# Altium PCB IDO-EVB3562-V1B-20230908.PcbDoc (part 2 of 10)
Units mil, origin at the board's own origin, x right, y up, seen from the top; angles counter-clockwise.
Board outline 5314.96 x 3543.31 mil, 4 copper layers (TOP, L2-VCC, L3-GND, BOTTOM), stack 28.8 mil thick; 747 components, 560 nets, 2514 pads, 1964 vias.
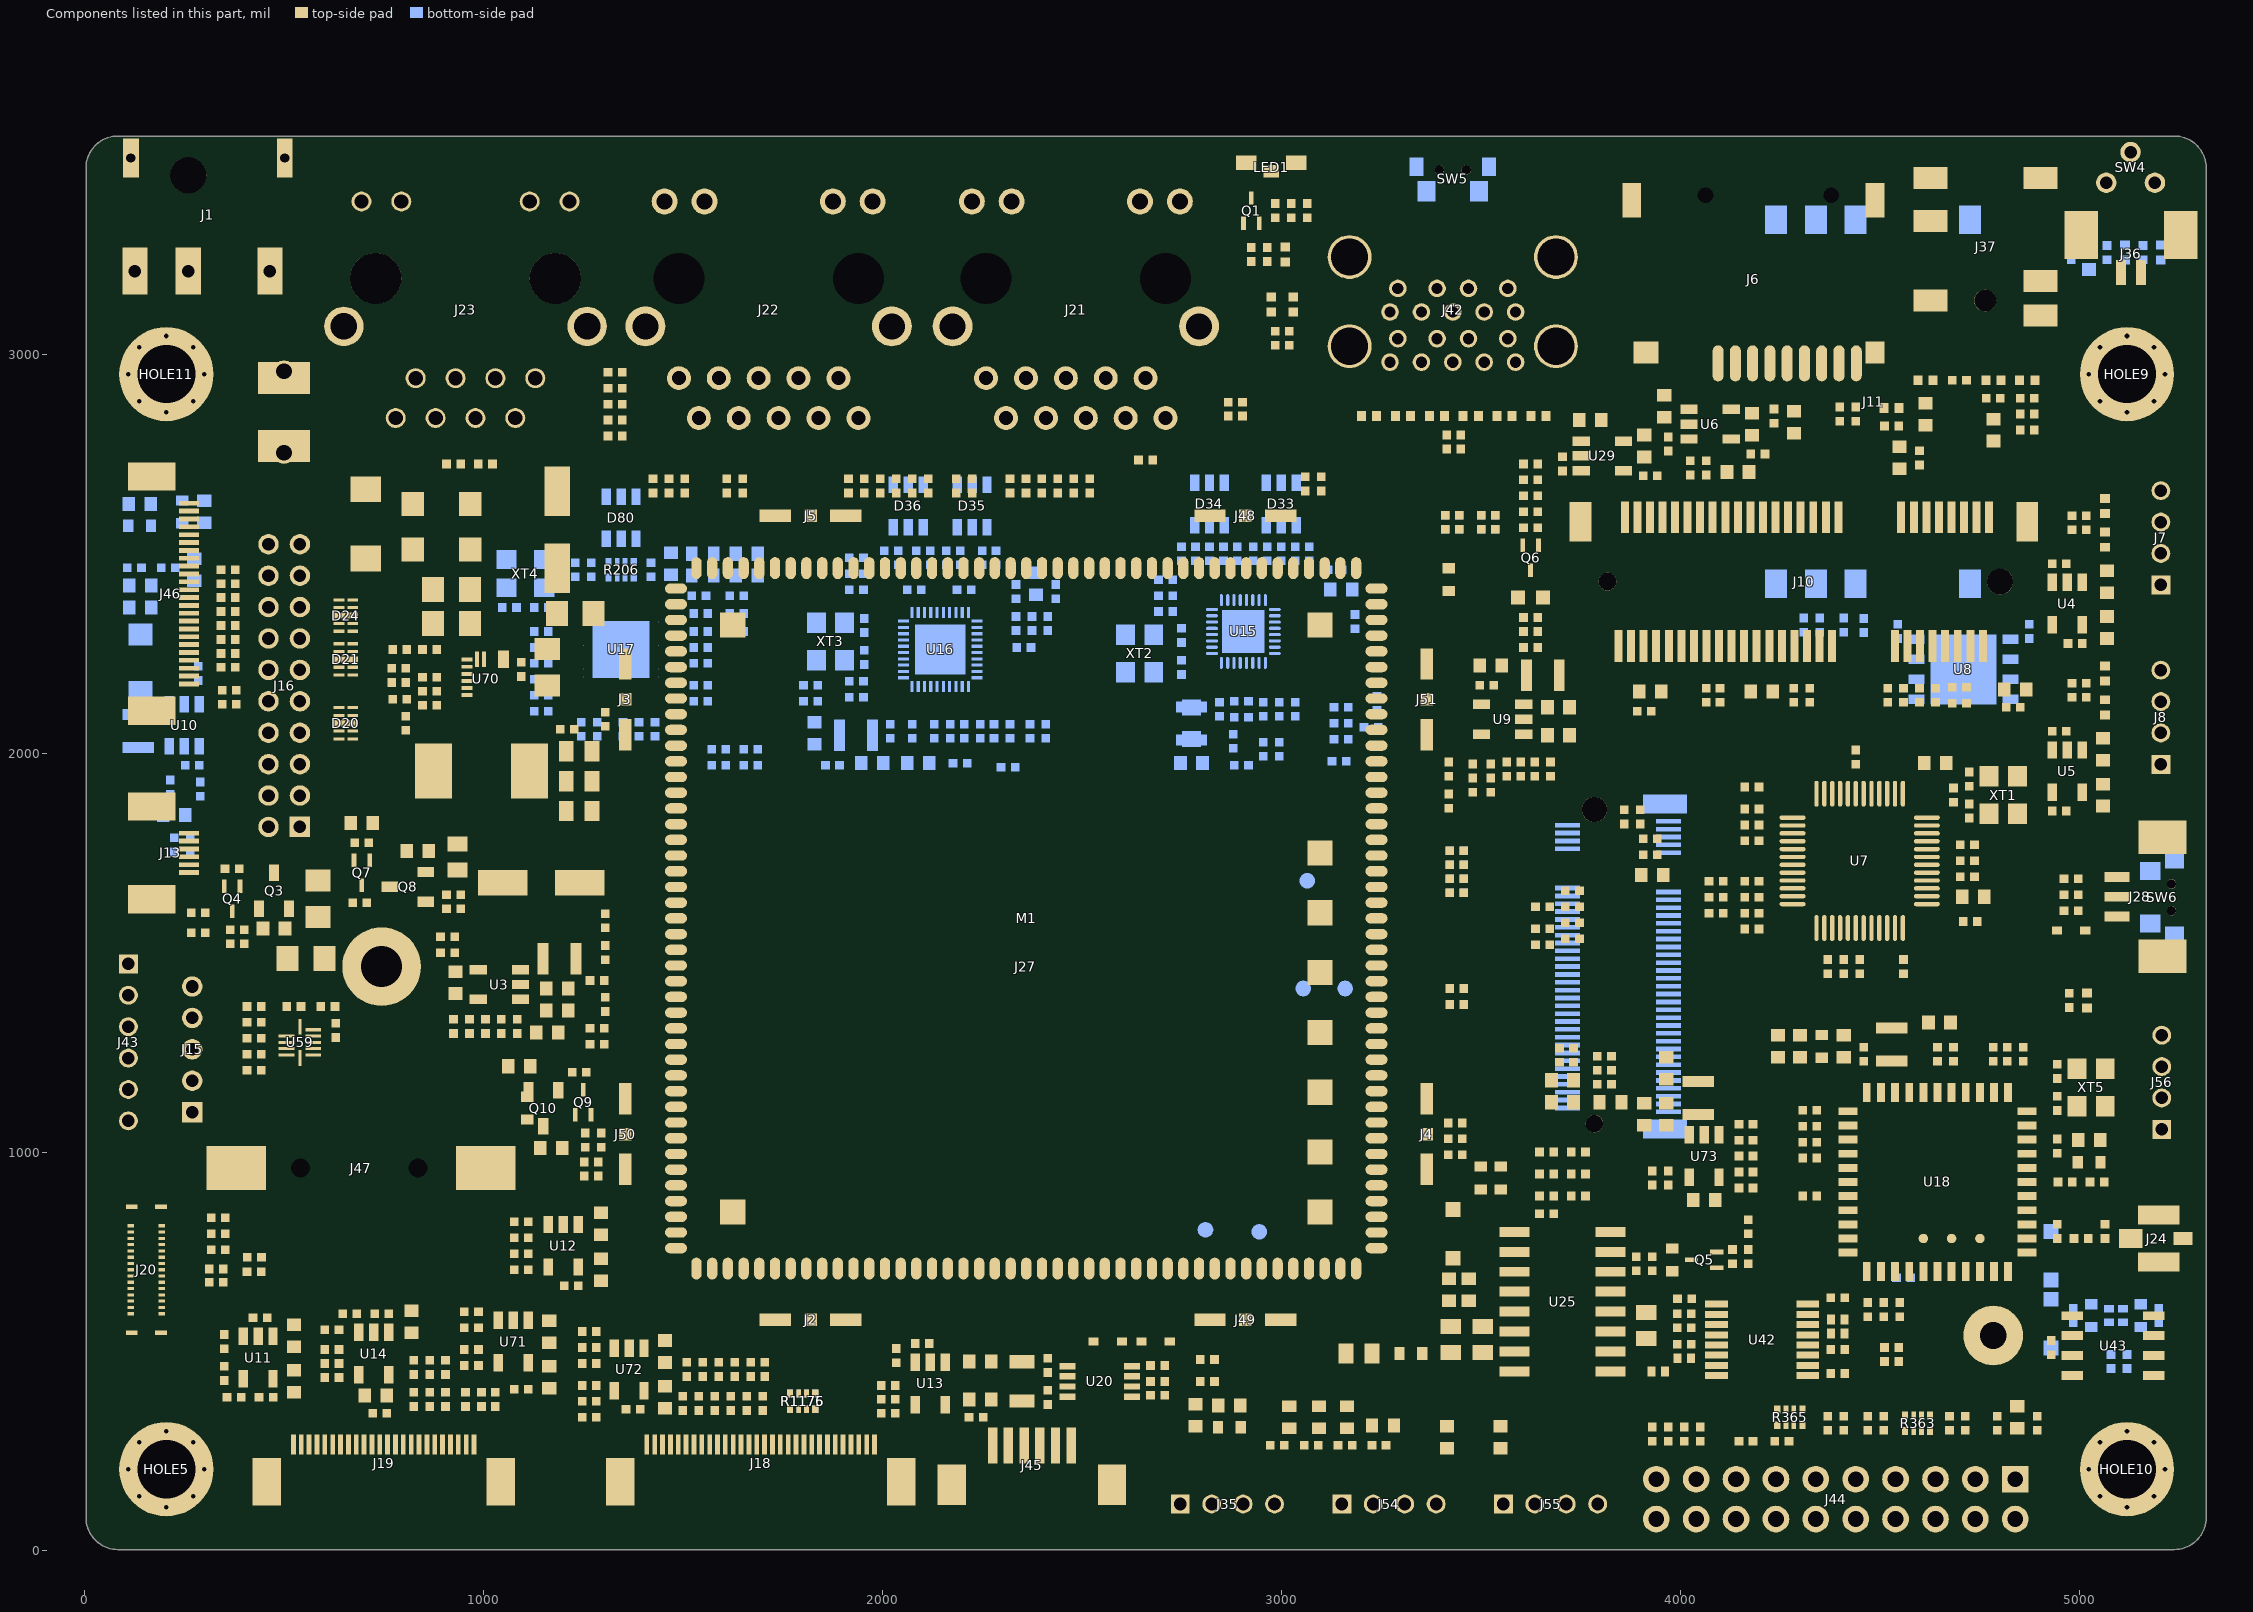
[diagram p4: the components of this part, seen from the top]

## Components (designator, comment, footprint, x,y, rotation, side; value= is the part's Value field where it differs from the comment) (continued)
SW4 "SW-3P_PB-SIDE-P-4_5X4_5_T-SWITC" ASSEMBLY_TOP#26 5128.98,3469.37 r270 top
SW5 "SW-TS24CA_PB-SIDE-S-3_5X4_5_T-S" SILKSCREEN_BOTTOM#6 3428.5,3440.5 r0 bottom
SW6 "SW-TS24CA_PB-SIDE-S-3_5X4_5_T-S" SILKSCREEN_BOTTOM#6 5210,1640 r270 bottom
TP1 "TP-TEST_TP100_TP100" ASSEMBLY_BOTTOM#7 3065,1680 r0 bottom
TP2 "TP-TEST_TP100_TP100" ASSEMBLY_BOTTOM#7 3055,1410 r0 bottom
TP3 "TP-TEST_TP100_TP100" ASSEMBLY_BOTTOM#7 3160,1410 r0 bottom
TP4 "TP-TEST_TP100_TP100" ASSEMBLY_BOTTOM#7 2945,800 r0 bottom
TP5 "TP-TEST_TP100_TP100" ASSEMBLY_BOTTOM#7 2810,805 r0 bottom
U3 "U-ETA3417S2F_SOT23-5_ETA3417S2F" SILKSCREEN_TOP#14 1040,1420 r180 top
U4 "U-SY6280AAC_SOT23-5_ETA6280S2F" SILKSCREEN_TOP#14 4970,2375 r270 top
U5 "U-SY6280AAC_SOT23-5_ETA6280S2F" SILKSCREEN_TOP#14 4970,1955 r270 top
U6 "U-SY6280AAC_SOT23-5_ETA6280S2F" ASSEMBLY_TOP#27 4075,2825 r0 top
U7 "U-FE1_1_LQFP-48_7X7X05P_FE1.1" ASSEMBLY_TOP#28 4450,1730 r180 top
U8 "ESIM_ESIM_NC/ESIM" ASSEMBLY_BOTTOM#8 4710,2210 r0 bottom
U9 "U-ETA3417S2F_SOT23-5_ETA3417S2F" SILKSCREEN_TOP#14 3555,2085 r180 top
U10 "U-SY7201ABC_SOT23-6_SY7201ABC" SILKSCREEN_BOTTOM#2 250,2070 r270 bottom
U11 "U-ETA5050_SOT23-5_ETA5050V0S2F" SILKSCREEN_TOP#14 435,485 r270 top
U12 "U-ETA5050_SOT23-5_ETA5050V0S2F" SILKSCREEN_TOP#14 1200,765 r270 top
U13 "U-ETA5050_SOT23-5_ETA5050V0S2F" SILKSCREEN_TOP#14 2120,420 r270 top
U14 "U-ETA5050_SOT23-5_ETA5050V0S2F" SILKSCREEN_TOP#14 725,495 r270 top
U15 "RL5877_0_QFN-32_4X4X04P_RTL8111" SILKSCREEN_BOTTOM#7 2905,2305 r270 bottom
U16 "U-RTL8211F-CG_QFN-40_5X5X04P_RT" SILKSCREEN_BOTTOM#8 2145,2260 r270 bottom
U17 "U-RTL8201F-VB-CG_QFN-32_5X5X05P" SILKSCREEN_BOTTOM#9 1345,2260 r270 bottom
U18 "MODULE_AP6XXX_MD44_AP6XXX_AP625" ASSEMBLY_TOP#29 4645,925 r180 top
U20 "U-HYM8563S_MSOP-8_HYM8563S" DISPLAY_TOP#17 2544.42,426.25 r0 top
U25 "U-NS4205_SOP16-P127-390X990_NS4" DISPLAY_TOP#18 3705,625 r180 top
U29 "U-SY6280AAC_SOT23-5_ETA6280S2F" SILKSCREEN_TOP#14 3805,2745 r0 top
U42 "U-SP3232EEN_TSSOP-16_HD3232ECY" ASSEMBLY_TOP#30 4205.5,529.14 r0 top
U43 "U-TJA1057GT-3J_SOP8-P127-390X49" ASSEMBLY_TOP#31 5085,515 r0 top
U59 "U-ETA4554QHM_ETA4554-QFN12_ETA4" ASSEMBLY_TOP#32 540,1275 r0 top
U70 "U-SY8368AQQC_6_QFN3X3-12-SY8368" SILKSCREEN_TOP#15 1010,2190 r90 top
U71 "U-ETA5050_SOT23-5_ETA5050V0S2F" SILKSCREEN_TOP#14 1075,525 r270 top
U72 "U-ETA5050_SOT23-5_ETA5050V0S2F" SILKSCREEN_TOP#14 1365,455 r270 top
U73 "U-ETA3417S2F_SOT23-5_ETA3417S2F" ASSEMBLY_TOP#27 4060,990 r270 top
XT1 "XTAL-4P_1_XTAL_32X25_4P_IC_12MH" SILKSCREEN_TOP#16 4810,1895 r180 top
XT2 "XTAL-4P_XTAL_32X25_4P_IC_25MHZ" ASSEMBLY_BOTTOM#9 2645,2250 r0 bottom
XT3 "XTAL-4P_XTAL_32X25_4P_IC_25MHZ" ASSEMBLY_BOTTOM#9 1870,2280 r0 bottom
XT4 "XTAL-4P_XTAL_32X25_4P_IC_25MHZ" ASSEMBLY_BOTTOM#10 1105,2450 r270 bottom
XT5 "XTAL-4P_XTAL_32X25_4P_IC_37.4MH" ASSEMBLY_TOP#33 5030,1162 r0 top
XT6 "XTAL-2P_XTAL_32X15_2P_IC_32.768" ASSEMBLY_TOP#34 2350,425 r270 top

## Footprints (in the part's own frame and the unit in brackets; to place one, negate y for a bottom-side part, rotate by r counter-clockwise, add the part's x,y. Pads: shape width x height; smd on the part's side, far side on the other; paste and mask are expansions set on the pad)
ASSEMBLY_BOTTOM#1 [mil] "ASSEMBLY_BOTTOM"
  rect 21.7x21.7 smd: 1(-17.72,0.01) 2(17.72,0.01)
  TOP keep-out region: -5,-14.99 -5,15.01 5,15.01 5,-14.99
  silkscreen extent -35,-16 35,16, body extent -35,-16 35,16, height 150
ASSEMBLY_BOTTOM#2 [mil] "ASSEMBLY_BOTTOM"
  rect 27.56x78.74 smd: 1(-40.84,0) 2(41.84,0)
  TOP keep-out region: -23.5,-40 -23.5,40 24.5,40 24.5,-40
  silkscreen extent -60,-45 60,45, body extent -58,-41 58,41, height 150
ASSEMBLY_BOTTOM#3 [mil] "ASSEMBLY_BOTTOM"
  rect 27.56x78.74 smd: 1(40.84,0) 2(-41.84,0)
  TOP keep-out region: 23.5,40 23.5,-40 -24.5,-40 -24.5,40 23.5,40
  silkscreen extent -60,-45 60,45, body extent -58,-41 58,41, height 150
ASSEMBLY_BOTTOM#4 [mil] "ASSEMBLY_BOTTOM"
  rect 27.56x78.74 smd: 1(-41.34,0) 2(41.34,0)
  TOP keep-out region: -24,-40 -24,40 24,40 24,-40 -24,-40
  silkscreen extent -60,-45 60,45
ASSEMBLY_BOTTOM#5 [mil] "ASSEMBLY_BOTTOM"
  rect 19.29x24.41 smd: 1(-16.93,0) 2(16.93,0)
  silkscreen extent -31,-16 31,16, body extent -31,-18 31,18, height 150
ASSEMBLY_BOTTOM#6 [mil] "ASSEMBLY_BOTTOM"
  rect 25.59x31.5 smd: 1(-28.54,0) 2(28.54,0)
  TOP keep-out region: -10,15 -10,-15 10,-15 10,15 -10,15
  silkscreen extent -53,-24 53,24, body extent -55,-25 55,25, height 150
ASSEMBLY_BOTTOM#7 [mil] "ASSEMBLY_BOTTOM"
  round 39.37 smd: 1(0,0)
  silkscreen extent -35,-35 35,35
ASSEMBLY_BOTTOM#8 [mil] "ASSEMBLY_BOTTOM"
  rect 40x24 smd: 1(118.11,-75) 2(118.11,-25) 3(118.11,25) 4(118.11,75) 5(-118.11,75) 6(-118.11,25) 7(-118.11,-25) 8(-118.11,-75)
  rect 166x176 smd: 9(0,0)
  silkscreen extent -118,-113 138,98, body extent -141,-101 141,101, height 150
ASSEMBLY_BOTTOM#9 [mil] "ASSEMBLY_BOTTOM"
  rect 47.24x51.18 smd: 1(35.43,-47.24) 2(35.43,47.24) 3(-35.43,47.24) 4(-35.43,-47.24)
  silkscreen extent -49,-63 76,63, body extent -59,-73 59,73, height 150
ASSEMBLY_BOTTOM#10 [mil] "ASSEMBLY_BOTTOM"
  rect 47.24x51.18 smd: 1(-35.43,47.24) 2(-35.43,-47.24) 3(35.43,-47.24) 4(35.43,47.24)
  silkscreen extent -76,-63 49,63, body extent -59,-73 59,73, height 150
ASSEMBLY_TOP#1 [mm] "ASSEMBLY_TOP"
  rect 3.15x1.6 smd: 1(-2.45,0) 2(2.45,0)
  silkscreen extent -3.92,-3.3 3.3,3.3, body extent -4.06,-3.9 4.55,3.43, height 3.81
ASSEMBLY_TOP#2 [mm] "ASSEMBLY_TOP"
  rect 0.8x0.899 smd: 1(-0.7,0) 2(0.7,0)
  silkscreen extent -1.35,-0.6 1.35,0.6, body extent -1.35,-0.6 1.35,0.6, height 3.81
ASSEMBLY_TOP#3 [mm] "ASSEMBLY_TOP"
  rect 0.551x0.551 smd: 1(-0.45,0) 2(0.45,0)
  TOP keep-out region: -0.127,-0.381 0.127,-0.381 0.127,0.381 -0.127,0.381 -0.127,-0.381
  silkscreen extent -0.9,-0.4 0.9,0.4, body extent -0.9,-0.4 0.9,0.4, height 3.81
ASSEMBLY_TOP#4 [mm] "ASSEMBLY_TOP"
  rect 0.95x1.3 smd: 1(-0.825,0) 2(0.825,0)
  silkscreen extent -1.7,-0.95 1.7,0.95, body extent -1.7,-0.95 1.7,0.95, height 3.81
ASSEMBLY_TOP#5 [mm] "ASSEMBLY_TOP"
  round 1.4 hole 0.991: 1(-2.591,0)
  round 1.4 / inner round 1.524 / far side round 1.4 hole 0.991: 2(2.591,0)
  silkscreen extent -6.86,-1.52 6.86,1.52, body extent -6.86,-1.52 6.86,1.52, height 3.81
ASSEMBLY_TOP#6 [mm] "ASSEMBLY_TOP"
  rect 2.032x3.302 smd: 1(-2.159,0) 2(2.159,0)
  TOP keep-out region: -1.6,1.699 -1.6,-1.699 1.6,-1.699 1.6,1.699 -1.6,1.699
  silkscreen extent -3.5,-1.9 3.5,1.9
ASSEMBLY_TOP#7 [mm] "ASSEMBLY_TOP"
  round 6 / inner round 1.524 / far side round 6 hole 3.7: 1(0,0)
  round 0.95 hole 0.3: ""(-2.425,0) ""(-1.715,-1.715) ""(-1.715,1.715) ""(0,-2.425) ""(0,2.425) ""(1.715,-1.715) ""(1.715,1.715)
  round 0 hole 0.3: ""(2.425,0)
  silkscreen extent -5.08,-5.08 5.08,5.08, body extent -3.01,-3.01 3.01,3.01, height 3.81
ASSEMBLY_TOP#8 [mm] "ASSEMBLY_TOP"
  rect 1.2x1.2 / inner round 1.524 / far side rect 1.2x1.2 hole 0.8: 1(3,-0.45)
  round 1.2 / inner round 1.524 / far side round 1.2 hole 0.8: 2(1,-0.45) 3(-1,-0.45)
  round 1.2 hole 0.8: 4(-3,-0.45)
  silkscreen extent -5,-2.25 5,2.25, body extent -5,-2.25 5,2.25, height 3.81
ASSEMBLY_TOP#9 [mm] "ASSEMBLY_TOP"
  rect 0.305x1.27 smd: 1(1.25,2.925) 2(0.75,2.925) 3(0.25,2.925) 4(-0.25,2.925) 5(-0.75,2.925) 6(-1.25,2.925)
  rect 1.803x3.048 smd: 7(2.95,0.55) 8(-2.95,0.55)
  silkscreen extent -4,-3.65 4,4.35, body extent -4,-3.65 4,3.65, height 3.81
ASSEMBLY_TOP#10 [mm] "ASSEMBLY_TOP"
  rect 1.3x1.3 / inner round 1 / far side rect 1.3x1.3 hole 0.8: 1(-4,0)
  round 1.3 / inner round 1.524 / far side round 1.3 hole 0.8: 2(-2,0) 3(0,0) 4(2,0)
  round 1.3 / inner round 1 / far side round 1.3 hole 0.8: 5(4,0)
  silkscreen extent -5,-2.15 5,1, body extent -5,-1 5,1, height 3.81
ASSEMBLY_TOP#11 [mm] "ASSEMBLY_TOP"
  rect 1.3x1.3 / inner round 1.524 / far side rect 1.3x1.3 hole 0.8: 1(-9,-1)
  round 1.3 / inner round 1.524 / far side round 1.3 hole 0.8: 2(-9,1) 3(-7,-1) 4(-7,1) 7(-3,-1) 8(-3,1) 9(-1,-1) 10(-1,1) 11(1,-1) 12(1,1) 15(5,-1) 16(5,1) 17(7,-1) 18(7,1) 19(9,-1) 20(9,1)
  round 1.3 / inner round 1 / far side round 1.3 hole 0.8: 5(-5,-1) 6(-5,1) 13(3,-1) 14(3,1)
  silkscreen extent -10,-3.1 10,2, body extent -10,-2 10,2, height 3.81
ASSEMBLY_TOP#12 [mm] "ASSEMBLY_TOP"
  rect 0.305x1.27 smd: 1(7.25,2.925) 2(6.75,2.925) 3(6.25,2.925) 4(5.75,2.925) 5(5.25,2.925) 6(4.75,2.925) 7(4.25,2.925) 8(3.75,2.925) 9(3.25,2.925) 10(2.75,2.925) 11(2.25,2.925) 12(1.75,2.925) 13(1.25,2.925) 14(0.75,2.925) 15(0.25,2.925) 16(-0.25,2.925) 17(-0.75,2.925) 18(-1.25,2.925) 19(-1.75,2.925) 20(-2.25,2.925) 21(-2.75,2.925) 22(-3.25,2.925) 23(-3.75,2.925) 24(-4.25,2.925) 25(-4.75,2.925) 26(-5.25,2.925) 27(-5.75,2.925) 28(-6.25,2.925) 29(-6.75,2.925) 30(-7.25,2.925)
  rect 1.803x3.048 smd: 31(8.95,0.55) 32(-8.95,0.55)
  silkscreen extent -10,-3.65 10.1,4.35, body extent -10,-3.65 10,3.65, height 3.81
ASSEMBLY_TOP#13 [mm] "ASSEMBLY_TOP"
  rect 0.305x1.27 smd: 1(5.75,2.925) 2(5.25,2.925) 3(4.75,2.925) 4(4.25,2.925) 5(3.75,2.925) 6(3.25,2.925) 7(2.75,2.925) 8(2.25,2.925) 9(1.75,2.925) 10(1.25,2.925) 11(0.75,2.925) 12(0.25,2.925) 13(-0.25,2.925) 14(-0.75,2.925) 15(-1.25,2.925) 16(-1.75,2.925) 17(-2.25,2.925) 18(-2.75,2.925) 19(-3.25,2.925) 20(-3.75,2.925) 21(-4.25,2.925) 22(-4.75,2.925) 23(-5.25,2.925) 24(-5.75,2.925)
  rect 1.803x3.048 smd: 25(7.45,0.55) 26(-7.45,0.55)
  silkscreen extent -8.5,-3.65 8.5,4.35, body extent -8.5,-3.65 8.5,3.65, height 3.81
ASSEMBLY_TOP#14 [mm] "ASSEMBLY_TOP"
  round 1.524 hole 0.889: 1(5.715,-9.14) 2(4.445,-6.6) 3(3.175,-9.14) 4(1.905,-6.6) 5(0.635,-9.14) 6(-0.635,-6.6) 7(-1.905,-9.14) 8(-3.175,-6.6) 9(-4.445,-9.14) 10(-5.715,-6.6)
  round 1.651 / inner round 1.524 / far side round 1.651 hole 1.016: 11(6.624,4.65) 12(4.084,4.65) 13(-4.084,4.65) 14(-6.624,4.65)
  round 2.54 hole 1.651: SH1(-7.846,-3.301) SH2(7.846,-3.301)
  round 2.997 hole 3.251 unplated: ""(-5.715,-0.25) ""(5.715,-0.25)
  Multi-Layer keep-out region: -3.495,-0.249 -3.537,0.184 -3.664,0.6 -3.869,0.984 -4.145,1.321 -4.481,1.597 -4.865,1.802 -5.282,1.928 -5.715,1.971 -6.148,1.928 -6.565,1.802 -6.82,1.665 -6.82,1.665 -6.949,1.597 -7.285,1.321 -7.561,0.984 -7.766,0.6 -7.893,0.184 -7.935,-0.249 -7.893,-0.683 -7.766,-1.099 -7.561,-1.483 -7.285,-1.82 -6.949,-2.096 -6.82,-2.164 -6.82,-2.164 -6.565,-2.301 -6.148,-2.427 -5.715,-2.47 -5.282,-2.427 -4.865,-2.301 -4.481,-2.096 -4.145,-1.82 -3.869,-1.483 -3.664,-1.099 -3.537,-0.683 -3.495,-0.249
  Multi-Layer keep-out region: 7.935,-0.249 7.893,0.184 7.766,0.6 7.561,0.984 7.285,1.321 6.949,1.597 6.565,1.802 6.148,1.928 5.715,1.971 5.282,1.928 4.865,1.802 4.61,1.665 4.61,1.665 4.481,1.597 4.145,1.321 3.869,0.984 3.664,0.6 3.537,0.184 3.495,-0.249 3.537,-0.683 3.664,-1.099 3.869,-1.483 4.145,-1.82 4.481,-2.096 4.61,-2.164 4.61,-2.164 4.865,-2.301 5.282,-2.427 5.715,-2.47 6.148,-2.427 6.565,-2.301 6.949,-2.096 7.285,-1.82 7.561,-1.483 7.766,-1.099 7.893,-0.683 7.935,-0.249
  silkscreen extent -8.1,-10.65 8.1,10.65, body extent -8.1,-10.65 8.1,10.65, height 3.81
ASSEMBLY_TOP#15 [mm] "ASSEMBLY_TOP"
  rect 1.2x0.8 smd: 1(-1.737,0)
  rect 1.5x1.2 smd: 2(1.587,0)
  rect 2.65x1.2 smd: 3(-0.212,-1.5) 4(-0.212,1.5)
  TOP keep-out region: 1.687,0.9 -1.112,0.9 -1.112,-0.9 1.687,-0.9 1.687,-0.503 1.439,-0.254 1.312,-0.127 1.312,0.127 1.687,0.503 1.687,0.9
  silkscreen extent -1.91,-1.63 1.75,1.62, body extent -2.34,-2.1 2.34,2.1, height 3.81
ASSEMBLY_TOP#16 [mm] "ASSEMBLY_TOP"
  rect 1.2x1.2 / inner round 1.524 / far side rect 1.2x1.2 hole 0.8: 1(3,-0.45)
  round 1.2 / inner round 1.524 / far side round 1.2 hole 0.8: 2(1,-0.45) 3(-1,-0.45) 4(-3,-0.45)
  silkscreen extent -5,-2.25 5,2.25, body extent -5,-2.25 5,2.25, height 3.81
ASSEMBLY_TOP#17 [mm] "ASSEMBLY_TOP"
  rect 1.4x2.159 smd: 1(2.55,3.446) 2(-4,-3.565) 3(-0.2,3.446) 4(2.55,-3.565) 5(-6.2,-3.565) 6(-5.25,3.446)
  round 1.397 hole 1.397 unplated: ""(-5.25,-0.05)
  silkscreen extent -6.8,-3.25 7.2,3.15, body extent -7.2,-4.85 7.2,4.85, height 3.81
ASSEMBLY_TOP#18 [mm] "ASSEMBLY_TOP"
  rect 1.2x1.2 / inner round 1.524 / far side rect 1.2x1.2 hole 0.8: 1(5,-0.45)
  round 1.2 / inner round 1.524 / far side round 1.2 hole 0.8: 2(3,-0.45) 3(1,-0.45) 4(-1,-0.45)
  round 1.2 hole 0.8: 5(-3,-0.45) 6(-5,-0.45)
  silkscreen extent -7,-2.25 7,2.25, body extent -7,-2.25 7,2.25, height 3.81
ASSEMBLY_TOP#19 [mm] "ASSEMBLY_TOP"
  rect 1.7x1.7 / inner round 1.524 / far side rect 1.7x1.7 hole 1: 1(-11.465,-1.255)
  round 1.7 / inner round 1.524 / far side round 1.7 hole 1: 2(-11.465,1.285) 3(-8.925,-1.255) 4(-8.925,1.285) 5(-6.385,-1.255) 6(-6.385,1.285) 7(-3.845,-1.255) 8(-3.845,1.285) 9(-1.305,-1.255) 10(-1.305,1.285) 11(1.235,-1.255) 12(1.235,1.285) 13(3.775,-1.255) 14(3.775,1.285) 15(6.315,-1.255) 16(6.315,1.285) 17(8.855,-1.255) 18(8.855,1.285) 20(11.395,1.285)
  round 1.7 hole 1: 19(11.395,-1.255)
  silkscreen extent -12.74,-3.53 12.66,2.55, body extent -12.74,-2.56 12.74,2.55, height 3.81
ASSEMBLY_TOP#20 [mm] "ASSEMBLY_TOP"
  rect 3.8x2.799 smd: 1(7.988,0.184) 2(-7.912,0.184)
  round 1.001 hole 1.199 unplated: ""(-3.822,0.184) ""(3.678,0.184)
  silkscreen extent -7.81,-7.32 8.16,7.76, body extent -9.92,-7.83 9.92,7.83, height 3.81
ASSEMBLY_TOP#21 [mm] "ASSEMBLY_TOP"
  rect 0.7x2 smd: 1(-1.037,0) 2(1.063,0)
  TOP keep-out region: -0.597,-1.016 0.622,-1.016 0.622,1.016 -0.597,1.016
  silkscreen extent -1.51,-1.14 1.54,1.14, body extent -1.46,-1.04 1.46,1.04, height 3.81
ASSEMBLY_TOP#22 [mm] "ASSEMBLY_TOP"
  rect 2.349x3.5 smd: 1(-3.048,0) 2(3.048,0)
  silkscreen extent -3.56,-3.43 3.56,3.43, body extent -3.56,-3.43 3.56,3.43, height 3.81
ASSEMBLY_TOP#23 [mm] "ASSEMBLY_TOP"
  rect 1.3x0.9 smd: 1(-1.6,0.25) 2(1.6,0.25)
  rect 1x0.8 smd: 3(0,0.8)
  silkscreen extent -1.6,-1.35 1.6,1.35, body extent -2.3,-1.45 2.3,1.45, height 3.81
ASSEMBLY_TOP#24 [mm] "ASSEMBLY_TOP"
  round 3.8 / inner round 2.5 / far side round 2.5 hole 1.7: 1(0,0)
  body extent -3.11,-3.11 3.11,3.11, height 3.81
ASSEMBLY_TOP#25 [mm] "ASSEMBLY_TOP"
  rect 0.65x0.8 smd: 1(-0.725,0) 2(0.725,0)
  TOP keep-out region: -0.254,0.381 -0.254,-0.381 0.254,-0.381 0.254,0.381 -0.254,0.381
  silkscreen extent -1.35,-0.6 1.35,0.6, body extent -1.4,-0.64 1.4,0.64, height 3.81
ASSEMBLY_TOP#26 [mm] "ASSEMBLY_TOP"
  round 1.3 / inner round 1.524 / far side round 1.3 hole 0.8: 1(1,1.55)
  round 1.3 hole 0.8: 2(1,-1.55) 3(-0.95,0)
  silkscreen extent -3.9,-2.35 1.8,2.35, body extent -1.8,-2.35 1.8,2.35, height 3.81
ASSEMBLY_TOP#27 [mm] "ASSEMBLY_TOP"
  rect 1.1x0.6 smd: 1(-1.35,0.95) 2(-1.35,0) 3(-1.35,-0.95) 4(1.35,-0.95) 5(1.35,0.95)
  silkscreen extent -2.03,-1.45 0.48,1.78, body extent -2.15,-1.8 2.03,1.8, height 3.81
ASSEMBLY_TOP#28 [mm] "ASSEMBLY_TOP"
  oval 1.651x0.279 smd: 1(-4.275,2.751) 2(-4.275,2.25) 3(-4.275,1.75) 4(-4.275,1.25) 5(-4.275,0.749) 6(-4.275,0.249) 7(-4.275,-0.249) 8(-4.275,-0.749) 9(-4.275,-1.25) 10(-4.275,-1.75) 11(-4.275,-2.25) 12(-4.275,-2.751) 25(4.275,-2.751) 26(4.275,-2.25) 27(4.275,-1.75) 28(4.275,-1.25) 29(4.275,-0.749) 30(4.275,-0.249) 31(4.275,0.249) 32(4.275,0.749) 33(4.275,1.25) 34(4.275,1.75) 35(4.275,2.25) 36(4.275,2.751)
  oval 0.279x1.651 smd: 13(-2.751,-4.275) 14(-2.25,-4.275) 15(-1.75,-4.275) 16(-1.25,-4.275) 17(-0.749,-4.275) 18(-0.249,-4.275) 19(0.249,-4.275) 20(0.749,-4.275) 21(1.25,-4.275) 22(1.75,-4.275) 23(2.25,-4.275) 24(2.751,-4.275) 37(2.751,4.275) 38(2.25,4.275) 39(1.75,4.275) 40(1.25,4.275) 41(0.749,4.275) 42(0.249,4.275) 43(-0.249,4.275) 44(-0.749,4.275) 45(-1.25,4.275) 46(-1.75,4.275) 47(-2.25,4.275) 48(-2.751,4.275)
  silkscreen extent -6.5,-6.5 6.5,5.99, body extent -4.5,-4.5 4.5,4.5, height 3.81
ASSEMBLY_TOP#29 [mm] "ASSEMBLY_TOP"
  rect 1.2x0.5 smd: 1(-5.7,4.5) 2(-5.7,3.6) 3(-5.7,2.7) 4(-5.7,1.8) 5(-5.7,0.9) 6(-5.7,0) 7(-5.7,-0.9) 8(-5.7,-1.8) 9(-5.7,-2.7) 10(-5.7,-3.6) 11(-5.7,-4.5) 23(5.7,-4.5) 24(5.7,-3.6) 25(5.7,-2.7) 26(5.7,-1.8) 27(5.7,-0.9) 28(5.7,0) 29(5.7,0.9) 30(5.7,1.8) 31(5.7,2.7) 32(5.7,3.6) 33(5.7,4.5)
  rect 0.5x1.2 smd: 12(-4.5,-5.7) 13(-3.6,-5.7) 14(-2.7,-5.7) 15(-1.8,-5.7) 16(-0.9,-5.7) 17(0,-5.7) 18(0.9,-5.7) 19(1.8,-5.7) 20(2.7,-5.7) 21(3.6,-5.7) 22(4.5,-5.7) 34(4.5,5.7) 35(3.6,5.7) 36(2.7,5.7) 37(1.8,5.7) 38(0.9,5.7) 39(0,5.7) 40(-0.9,5.7) 41(-1.8,5.7) 42(-2.7,5.7) 43(-3.6,5.7) 44(-4.5,5.7)
  round 0.6 smd: 45(-2.7,3.6) 46(-0.9,3.6) 47(0.9,3.6)
  silkscreen extent -7.17,-6 6,6, body extent -6.35,-6 6.35,6, height 3.81
ASSEMBLY_TOP#30 [mm] "ASSEMBLY_TOP"
  rect 1.45x0.45 smd: 1(-2.901,2.276) 2(-2.901,1.626) 3(-2.901,0.975) 4(-2.901,0.325) 5(-2.901,-0.325) 6(-2.901,-0.975) 7(-2.901,-1.626) 8(-2.901,-2.276) 9(2.901,-2.276) 10(2.901,-1.626) 11(2.901,-0.975) 12(2.901,-0.325) 13(2.901,0.325) 14(2.901,0.975) 15(2.901,1.626) 16(2.901,2.276)
  silkscreen extent -3.47,-2.5 1.85,3.12, body extent -3.9,-2.8 3.9,2.8, height 3.81
ASSEMBLY_TOP#31 [mm] "ASSEMBLY_TOP"
  rect 1.35x0.55 smd: 1(-2.6,1.905) 2(-2.6,0.635) 3(-2.6,-0.635) 4(-2.6,-1.905) 5(2.6,-1.905) 6(2.6,-0.635) 7(2.6,0.635) 8(2.6,1.905)
  silkscreen extent -3.12,-2.45 1.6,2.82, body extent -3.4,-2.6 3.4,2.6, height 3.81
ASSEMBLY_TOP#32 [mm] "ASSEMBLY_TOP"
  oct 0.025x0.025 smd: 1(-0.85,0.8)
  rect 1x0.2 smd: 2(-0.85,0.4) 3(-0.85,0) 4(-0.85,-0.4) 5(-0.85,-0.8) 7(0.85,-0.8) 8(0.85,-0.4) 9(0.85,0) 10(0.85,0.4) 11(0.85,0.8)
  rect 0.2x1 smd: 6(0,-1) 12(0,1)
  TOP region: -0.35,0.7 -0.35,1.5 -0.55,1.5 -0.55,0.9 -1.35,0.9 -1.35,0.7 -0.35,0.7
  TOP region: -0.35,0.7 -0.35,1.5 -0.55,1.5 -0.55,0.9 -1.35,0.9 -1.35,0.7 -0.35,0.7
  silkscreen extent -1.32,-1 0.85,1.65, body extent -0.85,-1 0.85,1, height 3.81
ASSEMBLY_TOP#33 [mm] "ASSEMBLY_TOP"
  rect 1.2x1.3 smd: 1(-0.9,1.2) 2(-0.9,-1.2) 3(0.9,-1.2) 4(0.9,1.2)
  silkscreen extent -1.25,-1.6 1.25,2.36, body extent -1.5,-1.85 1.5,1.85, height 3.81
ASSEMBLY_TOP#34 [mm] "ASSEMBLY_TOP"
  rect 0.85x1.6 smd: 1(-1.25,0) 2(1.25,0)
  silkscreen extent -1.91,-1.04 1.88,1.09, body extent -1.8,-0.95 1.8,0.95, height 3.81
DISPLAY_BOTTOM#1 [mil] "DISPLAY_BOTTOM"
  rect 21.7x21.7 smd: 1(-17.72,0.01) 2(17.72,0.01)
  TOP keep-out region: -5,-14.99 -5,15.01 5,15.01 5,-14.99
  silkscreen extent -35,-16 35,16, body extent -35,-16 35,16, height 150
DISPLAY_BOTTOM#2 [mil] "DISPLAY_BOTTOM"
  rect 31.5x35.4 smd: 1(27.56,0) 2(-27.56,0)
  silkscreen extent -53,-24 53,24, body extent -53,-24 53,24, height 150
DISPLAY_BOTTOM#3 [mil] "DISPLAY_BOTTOM"
  rect 31.5x35.4 smd: 1(-27.56,0) 2(27.56,0)
  silkscreen extent -53,-24 53,24, body extent -53,-24 53,24, height 150
DISPLAY_BOTTOM#4 [mil] "DISPLAY_BOTTOM"
  rect 21.7x21.7 smd: 1(17.72,-0.01) 2(-17.72,-0.01)
  TOP keep-out region: 5,14.99 5,-15.01 -5,-15.01 -5,14.99 5,14.99
  silkscreen extent -35,-16 35,16, body extent -35,-16 35,16, height 150
DISPLAY_BOTTOM#5 [mil] "DISPLAY_BOTTOM"
  rect 22.44x24.41 smd: 1(-18.9,0) 2(18.9,0)
  silkscreen extent -38,-21 39,21, body extent -36,-18 36,18, height 150
DISPLAY_BOTTOM#6 [mil] "DISPLAY_BOTTOM"
  rect 29.53x35.43 smd: 1(27.56,0) 2(-27.56,0)
  silkscreen extent -47,-24 47,24, body extent -47,-24 47,24, height 150
DISPLAY_BOTTOM#7 [mil] "DISPLAY_BOTTOM"
  rect 29.53x35.43 smd: 1(-27.56,0) 2(27.56,0)
  silkscreen extent -47,-24 47,24, body extent -47,-24 47,24, height 150
DISPLAY_BOTTOM#8 [mil] "DISPLAY_BOTTOM"
  rect 19.7x15.7 smd: 1(-19.68,31.5) 4(-19.68,-31.5) 5(19.68,-31.5) 8(19.68,31.5)
  rect 19.7x11.8 smd: 2(-19.68,9.84) 3(-19.68,-9.84) 6(19.68,-9.84) 7(19.68,9.84)
  silkscreen extent -38,-50 38,50, body extent -35,-47 35,47, height 150
DISPLAY_BOTTOM#9 [mil] "DISPLAY_BOTTOM"
  rect 25.59x31.5 smd: 1(-28.54,0) 2(28.54,0)
  TOP keep-out region: -10,15 -10,-15 10,-15 10,15 -10,15
  silkscreen extent -53,-24 53,24, body extent -55,-25 55,25, height 150
DISPLAY_BOTTOM#10 [mil] "DISPLAY_BOTTOM"
  rect 39.37x47.24 smd: 1(-39.37,0) 2(39.37,0)
  TOP keep-out region: -15,25 -15,-25 15,-25 15,25 -15,25
  silkscreen extent -67,-37 67,37, body extent -70,-40 70,40, height 150
DISPLAY_TOP#1 [mm] "DISPLAY_TOP"
  rect 1.4x1.6 smd: 1(-1.168,0) 2(1.168,0)
  silkscreen extent -2.2,-1 2.2,1, body extent -2.2,-1 2.2,1, height 3.81
DISPLAY_TOP#2 [mm] "DISPLAY_TOP"
  rect 0.8x0.899 smd: 1(-0.7,0) 2(0.7,0)
  silkscreen extent -1.35,-0.6 1.35,0.6, body extent -1.35,-0.6 1.35,0.6, height 3.81
DISPLAY_TOP#3 [mm] "DISPLAY_TOP"
  rect 0.551x0.551 smd: 1(-0.45,0) 2(0.45,0)
  TOP keep-out region: -0.127,-0.381 0.127,-0.381 0.127,0.381 -0.127,0.381
  silkscreen extent -0.9,-0.4 0.9,0.4, body extent -0.9,-0.4 0.9,0.4, height 3.81
DISPLAY_TOP#4 [mm] "DISPLAY_TOP"
  rect 0.95x1.3 smd: 1(-0.825,0) 2(0.825,0)
  silkscreen extent -1.7,-0.95 1.7,0.95, body extent -1.7,-0.95 1.7,0.95, height 3.81
DISPLAY_TOP#5 [mm] "DISPLAY_TOP"
  rect 1.65x1.95 smd: A(2.2,0) C(-2.2,0)
  silkscreen extent -3.67,-1.8 2.65,1.8, body extent -3.15,-2.1 3.15,2.1, height 3.81
DISPLAY_TOP#6 [mm] "DISPLAY_TOP"
  rect 0.57x0.62 smd: 1(-0.48,0) 2(0.48,0)
  silkscreen extent -0.97,-0.53 1,0.52, body extent -0.92,-0.46 0.92,0.46, height 3.81
DISPLAY_TOP#7 [mm] "DISPLAY_TOP"
  rect 0.2x0.68 smd: 1(-1,-0.437) 2(-0.5,-0.437) 4(0.5,-0.437) 5(1,-0.437) 6(1,0.437) 7(0.5,0.437) 9(-0.5,0.437) 10(-1,0.437)
  rect 0.4x0.75 smd: 3(0,-0.395) 8(0,0.395)
  silkscreen extent -1.43,-0.5 1.25,1.69, body extent -1.39,-0.64 1.39,0.64, height 3.81
DISPLAY_TOP#8 [mm] "DISPLAY_TOP"
  rect 0.65x0.5 smd: A(0.9,0) C(-0.9,0)
  silkscreen extent -1.23,-0.58 0.6,0.87, body extent -1.5,-0.7 1.5,0.7, height 3.81
DISPLAY_TOP#9 [mm] "DISPLAY_TOP"
  rect 0.8x0.8 smd: 1(-0.013,-0.01)
  rect 2x0.8 smd: 2(-2.263,-0.01) 3(2.237,-0.01)
  silkscreen extent -3.36,-0.46 3.34,0.44, body extent -3.34,-0.51 3.34,0.51, height 3.81
DISPLAY_TOP#10 [mm] "DISPLAY_TOP"
  rect 0.75x0.9 smd: 1(-0.7,0) 2(0.7,0)
  silkscreen extent -1.2,-0.6 1.2,0.6, body extent -1.2,-0.6 1.2,0.6, height 3.81
DISPLAY_TOP#11 [mm] "DISPLAY_TOP"
  rect 0.49x0.62 smd: 1(-0.43,0) 2(0.43,0)
  silkscreen extent -0.8,-0.4 0.8,0.4, body extent -0.78,-0.45 0.78,0.45, height 3.81
DISPLAY_TOP#12 [mm] "DISPLAY_TOP"
  rect 0.85x0.3 smd: 1(-0.8,0.5) 2(-0.8,-0.5) 3(0.8,0)
  silkscreen extent -1.07,-0.8 0,1.27, body extent -1.5,-1.1 1.5,1.1, height 3.81
DISPLAY_TOP#13 [mm] "DISPLAY_TOP"
  rect 1.05x0.65 smd: 1(-1.15,0.95) 2(-1.15,-0.95) 3(1.15,0)
  silkscreen extent -1.52,-1.45 0.3,1.92, body extent -1.78,-1.75 1.95,1.75, height 3.81
DISPLAY_TOP#14 [mm] "DISPLAY_TOP"
  rect 0.65x0.8 smd: 1(-0.725,0) 2(0.725,0)
  TOP keep-out region: -0.254,0.381 -0.254,-0.381 0.254,-0.381 0.254,0.381 -0.254,0.381
  silkscreen extent -1.35,-0.6 1.35,0.6, body extent -1.4,-0.64 1.4,0.64, height 3.81
DISPLAY_TOP#15 [mm] "DISPLAY_TOP"
  rect 0.5x0.399 smd: 1(-0.5,0.8) 4(-0.5,-0.8) 5(0.5,-0.8) 8(0.5,0.8)
  rect 0.5x0.3 smd: 2(-0.5,0.25) 3(-0.5,-0.25) 6(0.5,-0.25) 7(0.5,0.25)
  silkscreen extent -0.98,-1.28 0.98,1.28, body extent -0.9,-1.2 0.9,1.2, height 3.81
DISPLAY_TOP#16 [mm] "DISPLAY_TOP"
  rect 0.551x0.551 smd: 1(0.45,0) 2(-0.45,0)
  TOP keep-out region: 0.127,-0.381 0.127,0.381 -0.127,0.381 -0.127,-0.381 0.127,-0.381
  silkscreen extent -0.9,-0.4 0.9,0.4, body extent -0.89,-0.38 0.89,0.38, height 3.81
DISPLAY_TOP#17 [mm] "DISPLAY_TOP"
  rect 1x0.4 smd: 1(-2.035,0.943) 2(-2.035,0.293) 3(-2.035,-0.357) 4(-2.035,-1.007) 5(2.065,-1.007) 6(2.065,-0.357) 7(2.065,0.293) 8(2.065,0.943)
  silkscreen extent -2.68,-1.56 1.41,1.87, body extent -2.75,-1.62 2.75,1.62, height 3.81
DISPLAY_TOP#18 [mm] "DISPLAY_TOP"
  rect 1.905x0.635 smd: 1(-3.048,4.445) 2(-3.048,3.175) 3(-3.048,1.905) 4(-3.048,0.635) 5(-3.048,-0.635) 6(-3.048,-1.905) 7(-3.048,-3.175) 8(-3.048,-4.445) 9(3.048,-4.445) 10(3.048,-3.175) 11(3.048,-1.905) 12(3.048,-0.635) 13(3.048,0.635) 14(3.048,1.905) 15(3.048,3.175) 16(3.048,4.445)
  silkscreen extent -5.09,-4.95 1.91,4.95, body extent -4.06,-4.95 4.06,4.95, height 3.81
SILKSCREEN_BOTTOM#1 [mm] "SILKSCREEN_BOTTOM"
  rect 1.43x1.53 smd: A(-1.84,0) C(1.84,0)
  silkscreen extent -1.75,-1.3 2.42,1.4, body extent -2.66,-1.45 2.66,1.45, height 3.81
SILKSCREEN_BOTTOM#2 [mm] "SILKSCREEN_BOTTOM"
  rect 1.05x0.6 smd: 1(-1.35,0.95) 2(-1.35,0) 3(-1.35,-0.95) 4(1.35,-0.95) 5(1.35,0) 6(1.35,0.95)
  silkscreen extent -1.72,-1.5 0.5,1.88, body extent -2.15,-1.8 2.15,1.8, height 3.81
SILKSCREEN_BOTTOM#3 [mm] "SILKSCREEN_BOTTOM"
  rect 0.94x0.95 smd: A(-1.55,0) C(1.55,0)
  silkscreen extent -0.6,-0.8 1.97,1.11, body extent -2.02,-0.95 2.02,0.95, height 3.81
SILKSCREEN_BOTTOM#4 [mm] "SILKSCREEN_BOTTOM"
  rect 1.829x1.397 smd: C1(13.299,2.119) C2(13.299,-0.421) C3(13.299,-2.961) C5(-9.872,2.119) C6(-9.872,-0.421) C7(-9.872,-2.961) CD1(13.299,-10.251) CD2(-9.872,-10.251)
  silkscreen extent -16.98,-12.51 17.02,12.49, body extent -17.05,-12.5 17.05,12.5, height 3.81
SILKSCREEN_BOTTOM#5 [mm] "SILKSCREEN_BOTTOM"
  rect 1.6x0.3 smd: 1(40.285,9.25) 2(33.835,9) 3(40.285,8.75) 4(33.835,8.5) 5(40.285,8.25) 6(33.835,8) 7(40.285,7.75) 8(33.835,7.5) 9(40.285,7.25) 10(33.835,7) 11(40.285,6.75) 12(33.835,6.5) 13(40.285,6.25) 14(33.835,6) 15(40.285,5.75) 16(33.835,5.5) 17(40.285,5.25) 18(33.835,5) 19(40.285,4.75) 20(33.835,4.5) 21(40.285,4.25) 22(33.835,4) 23(40.285,3.75) 24(33.835,3.5) 25(40.285,3.25) 26(33.835,3) 27(40.285,2.75) 28(33.835,2.5) 29(40.285,2.25) 30(33.835,2) 31(40.285,1.75) 32(33.835,1.5) 33(40.285,1.25) 34(33.835,1) 35(40.285,0.75) 36(33.835,0.5) 37(40.285,0.25) 38(33.835,0) 39(40.285,-0.25) 40(33.835,-0.5) 41(40.285,-0.75) 42(33.835,-1) 43(40.285,-1.25) 44(33.835,-1.5) 45(40.285,-1.75) 46(33.835,-2) 47(40.285,-2.25) 48(33.835,-2.5) 49(40.285,-2.75) 50(33.835,-3) 51(40.285,-3.25) 52(33.835,-3.5) 53(40.285,-3.75) 54(33.835,-4) 55(40.285,-4.25) 56(33.835,-4.5) 57(40.285,-4.75) 58(33.835,-5) 67(40.285,-7.25) 68(33.835,-7.5) 69(40.285,-7.75) 70(33.835,-8) 71(40.285,-8.25) 72(33.835,-8.5) 73(40.285,-8.75) 74(33.835,-9) 75(40.285,-9.25)
  round 1.118 / inner round 1.524 / far side round 1.118 hole 1.118 unplated: 77(35.56,10)
  round 1.6 / inner round 1.524 / far side round 1.6 hole 1.6 unplated: 78(35.56,-10)
  rect 2.8x1.2 smd: G1(40.06,-10.35) G2(40.06,10.35)
  round 4.5 / inner round 1.524 / far side round 5 hole 2.6: G3(-41.664,0)
  round 1.27 hole 1.016: G4(-41.664,0)
  silkscreen extent -41.78,-11.18 41.78,11.18, body extent -41.91,-11.18 41.91,11.18, height 3.81
SILKSCREEN_BOTTOM#6 [mm] "SILKSCREEN_BOTTOM"
  rect 0.9x1.2 smd: 1(2.339,-0.749) 2(-2.263,-0.749)
  rect 1.15x1.3 smd: 3(1.713,0.801) 4(-1.637,0.801)
  round 0.6 hole 0.6 unplated: ""(-0.813,-0.546) ""(0.889,-0.546)
  silkscreen extent -2.86,-2.65 2.94,1.55, body extent -2.86,-1.44 2.86,1.44, height 3.81
SILKSCREEN_BOTTOM#7 [mm] "SILKSCREEN_BOTTOM"
  oval 0.762x0.203 smd: 1(-2,1.4) 2(-2,1) 3(-2,0.6) 4(-2,0.2) 5(-2,-0.2) 6(-2,-0.6) 7(-2,-1) 8(-2,-1.4) 17(2,-1.4) 18(2,-1) 19(2,-0.6) 20(2,-0.2) 21(2,0.2) 22(2,0.6) 23(2,1) 24(2,1.4)
  oval 0.203x0.762 smd: 9(-1.4,-2) 10(-1,-2) 11(-0.6,-2) 12(-0.2,-2) 13(0.2,-2) 14(0.6,-2) 15(1,-2) 16(1.4,-2) 25(1.4,2) 26(1,2) 27(0.6,2) 28(0.2,2) 29(-0.2,2) 30(-0.6,2) 31(-1,2) 32(-1.4,2)
  rect 2.718x2.718 smd: 33(0,0)
  silkscreen extent -2,-2 2,2, body extent -2.38,-2.38 2.38,2.38, height 3.81
SILKSCREEN_BOTTOM#8 [mm] "SILKSCREEN_BOTTOM"
  rect 0.7x0.2 smd: 1(-2.35,1.8) 2(-2.35,1.4) 3(-2.35,1) 4(-2.35,0.6) 5(-2.35,0.2) 6(-2.35,-0.2) 7(-2.35,-0.6) 8(-2.35,-1) 9(-2.35,-1.4) 10(-2.35,-1.8) 21(2.35,-1.8) 22(2.35,-1.4) 23(2.35,-1) 24(2.35,-0.6) 25(2.35,-0.2) 26(2.35,0.2) 27(2.35,0.6) 28(2.35,1) 29(2.35,1.4) 30(2.35,1.8)
  rect 0.2x0.7 smd: 11(-1.8,-2.35) 12(-1.4,-2.35) 13(-1,-2.35) 14(-0.6,-2.35) 15(-0.2,-2.35) 16(0.2,-2.35) 17(0.6,-2.35) 18(1,-2.35) 19(1.4,-2.35) 20(1.8,-2.35) 31(1.8,2.35) 32(1.4,2.35) 33(1,2.35) 34(0.6,2.35) 35(0.2,2.35) 36(-0.2,2.35) 37(-0.6,2.35) 38(-1,2.35) 39(-1.4,2.35) 40(-1.8,2.35)
  rect 3.2x3.2 smd: 41(0,0)
  silkscreen extent -3.1,-2.5 2.5,2.5, body extent -2.6,-2.6 2.6,2.6, height 3.81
